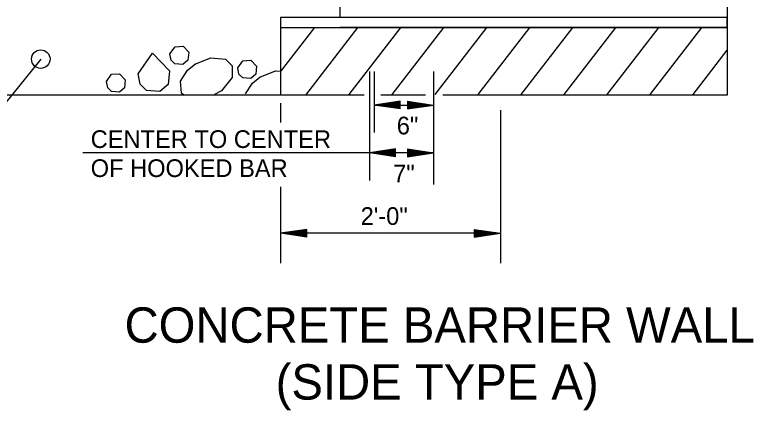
# Model space of a CAD drawing. Extents: x 714919 to 718439, y 1619644 to 1621844.
# Drawn here: x 717627.5 to 718060.8, y 1620274.3 to 1620506.3 of the extents above; entities that cross this region are included whole.
import ezdxf

# ---------------------------------------------------------------- set-up
doc = ezdxf.new("R2010")
doc.units = 0
for name, color, linetype in [('R_Annotation', 7, 'Continuous'), ('R_Dimension', 7, 'Continuous'), ('T_Drafting', 7, 'Continuous')]:
    doc.layers.add(name, color=color, linetype=linetype)

msp = doc.modelspace()

# ---------------------------------------------------------------- linework, layer by layer
at = {"layer": 'R_Annotation'}
msp.add_line((717642.78, 1620480.25), (717587.69, 1620412.31), dxfattribs=at)
msp.add_circle((717642.78, 1620480.25), 5.43, dxfattribs=at)
at = {"layer": 'R_Dimension'}
for p, q in [((717835.7, 1620472.99), (717835.7, 1620409.04)), ((717838.43, 1620472.99), (717838.43, 1620437.15)), ((717873.25, 1620472.99), (717873.25, 1620434.82)), ((717853.72, 1620455.64), (717838.43, 1620453.31)), ((717853.72, 1620455.3), (717840.93, 1620453.31)), ((717853.72, 1620454.86), (717843.61, 1620453.31)), ((717853.72, 1620451.06), (717853.72, 1620455.64)), ((717857.95, 1620455.64), (717873.25, 1620453.31)), ((717857.95, 1620455.64), (717857.95, 1620451.06)), ((717857.95, 1620455.64), (717873.25, 1620453.31)), ((717857.95, 1620455.64), (717857.95, 1620451.06)), ((717857.95, 1620455.3), (717870.74, 1620453.31)), ((717857.95, 1620455.3), (717870.74, 1620453.31)), ((717857.95, 1620454.86), (717868.06, 1620453.31)), ((717857.95, 1620454.86), (717868.06, 1620453.31)), ((717783.48, 1620454.51), (717783.48, 1620443.02)), ((717853.72, 1620451.06), (717838.43, 1620453.31)), ((717838.43, 1620453.31), (717869.36, 1620453.31)), ((717853.72, 1620451.41), (717840.93, 1620453.31)), ((717853.72, 1620451.84), (717843.61, 1620453.31)), ((717853.72, 1620454.52), (717846.12, 1620453.31)), ((717853.72, 1620452.19), (717846.12, 1620453.31)), ((717853.72, 1620454.09), (717848.71, 1620453.31)), ((717853.72, 1620452.62), (717848.71, 1620453.31)), ((717853.72, 1620453.74), (717851.3, 1620453.31)), ((717853.72, 1620452.96), (717851.3, 1620453.31)), ((717857.95, 1620454.52), (717865.56, 1620453.31)), ((717857.95, 1620454.52), (717865.56, 1620453.31)), ((717857.95, 1620454.09), (717862.96, 1620453.31)), ((717857.95, 1620454.09), (717862.96, 1620453.31)), ((717857.95, 1620453.74), (717860.37, 1620453.31)), ((717857.95, 1620453.74), (717860.37, 1620453.31)), ((717857.95, 1620451.06), (717873.25, 1620453.31)), ((717857.95, 1620452.62), (717862.96, 1620453.31)), ((717857.95, 1620451.84), (717868.06, 1620453.31)), ((717857.95, 1620451.41), (717870.74, 1620453.31)), ((717857.95, 1620452.19), (717865.56, 1620453.31)), ((717857.95, 1620452.96), (717860.37, 1620453.31)), ((717857.95, 1620451.06), (717873.25, 1620453.31)), ((717857.95, 1620452.62), (717862.96, 1620453.31)), ((717857.95, 1620451.84), (717868.06, 1620453.31)), ((717857.95, 1620451.41), (717870.74, 1620453.31)), ((717857.95, 1620452.19), (717865.56, 1620453.31)), ((717857.95, 1620452.96), (717860.37, 1620453.31)), ((717912.47, 1620450.4), (717912.47, 1620360.51)), ((717873.25, 1620434.82), (717873.25, 1620406.71)), ((717873.25, 1620425.2), (717667.38, 1620425.2)), ((717850.99, 1620427.53), (717835.7, 1620425.2)), ((717850.99, 1620422.95), (717835.7, 1620425.2)), ((717850.99, 1620427.19), (717838.2, 1620425.2)), ((717850.99, 1620423.3), (717838.2, 1620425.2)), ((717850.99, 1620426.75), (717840.88, 1620425.2)), ((717850.99, 1620423.73), (717840.88, 1620425.2)), ((717850.99, 1620426.41), (717843.39, 1620425.2)), ((717850.99, 1620424.08), (717843.39, 1620425.2)), ((717850.99, 1620425.98), (717845.98, 1620425.2)), ((717850.99, 1620424.51), (717845.98, 1620425.2)), ((717850.99, 1620425.63), (717848.57, 1620425.2)), ((717850.99, 1620424.85), (717848.57, 1620425.2)), ((717850.99, 1620422.95), (717850.99, 1620427.53)), ((717857.95, 1620427.53), (717873.25, 1620425.2)), ((717857.95, 1620427.53), (717857.95, 1620422.95)), ((717857.95, 1620427.53), (717873.25, 1620425.2)), ((717857.95, 1620427.53), (717857.95, 1620422.95)), ((717857.95, 1620427.19), (717870.74, 1620425.2)), ((717857.95, 1620427.19), (717870.74, 1620425.2)), ((717857.95, 1620426.75), (717868.06, 1620425.2)), ((717857.95, 1620426.75), (717868.06, 1620425.2)), ((717857.95, 1620426.41), (717865.56, 1620425.2)), ((717857.95, 1620426.41), (717865.56, 1620425.2)), ((717857.95, 1620425.98), (717862.96, 1620425.2)), ((717857.95, 1620425.98), (717862.96, 1620425.2)), ((717857.95, 1620425.63), (717860.37, 1620425.2)), ((717857.95, 1620425.63), (717860.37, 1620425.2)), ((717857.95, 1620422.95), (717873.25, 1620425.2)), ((717857.95, 1620424.51), (717862.96, 1620425.2)), ((717857.95, 1620423.73), (717868.06, 1620425.2)), ((717857.95, 1620423.3), (717870.74, 1620425.2)), ((717857.95, 1620424.08), (717865.56, 1620425.2)), ((717857.95, 1620424.85), (717860.37, 1620425.2)), ((717857.95, 1620422.95), (717873.25, 1620425.2)), ((717857.95, 1620424.51), (717862.96, 1620425.2)), ((717857.95, 1620423.73), (717868.06, 1620425.2)), ((717857.95, 1620423.3), (717870.74, 1620425.2)), ((717857.95, 1620424.08), (717865.56, 1620425.2)), ((717857.95, 1620424.85), (717860.37, 1620425.2)), ((717783.48, 1620405.26), (717783.48, 1620360.51)), ((717798.86, 1620380.38), (717783.48, 1620378.05)), ((717798.86, 1620380.38), (717783.48, 1620378.05)), ((717898.99, 1620378.05), (717783.48, 1620378.05)), ((717798.86, 1620375.8), (717783.48, 1620378.05)), ((717798.86, 1620375.8), (717783.48, 1620378.05)), ((717798.86, 1620379.95), (717786.07, 1620378.05)), ((717798.86, 1620379.95), (717786.07, 1620378.05)), ((717798.86, 1620376.15), (717786.07, 1620378.05)), ((717798.86, 1620376.15), (717786.07, 1620378.05)), ((717798.86, 1620379.6), (717788.75, 1620378.05)), ((717798.86, 1620379.6), (717788.75, 1620378.05)), ((717798.86, 1620376.58), (717788.75, 1620378.05)), ((717798.86, 1620376.58), (717788.75, 1620378.05)), ((717798.86, 1620379.26), (717791.25, 1620378.05)), ((717798.86, 1620379.26), (717791.25, 1620378.05)), ((717798.86, 1620376.92), (717791.25, 1620378.05)), ((717798.86, 1620376.92), (717791.25, 1620378.05)), ((717798.86, 1620378.82), (717793.84, 1620378.05)), ((717798.86, 1620378.82), (717793.84, 1620378.05)), ((717798.86, 1620377.27), (717793.84, 1620378.05)), ((717798.86, 1620377.27), (717793.84, 1620378.05)), ((717798.86, 1620378.48), (717796.35, 1620378.05)), ((717798.86, 1620378.48), (717796.35, 1620378.05)), ((717798.86, 1620377.7), (717796.35, 1620378.05)), ((717798.86, 1620377.7), (717796.35, 1620378.05)), ((717798.86, 1620375.8), (717798.86, 1620380.38)), ((717798.86, 1620375.8), (717798.86, 1620380.38)), ((717897.09, 1620380.38), (717912.47, 1620378.05)), ((717897.09, 1620380.38), (717897.09, 1620375.8)), ((717897.09, 1620379.95), (717909.97, 1620378.05)), ((717897.09, 1620379.6), (717907.2, 1620378.05)), ((717897.09, 1620379.26), (717904.7, 1620378.05)), ((717897.09, 1620378.82), (717902.1, 1620378.05)), ((717897.09, 1620378.48), (717899.6, 1620378.05)), ((717897.09, 1620375.8), (717912.47, 1620378.05)), ((717897.09, 1620377.27), (717902.1, 1620378.05)), ((717897.09, 1620376.58), (717907.2, 1620378.05)), ((717897.09, 1620376.15), (717909.97, 1620378.05)), ((717897.09, 1620376.92), (717904.7, 1620378.05)), ((717897.09, 1620377.7), (717899.6, 1620378.05))]:
    msp.add_line(p, q, dxfattribs=at)
at = {"layer": 'T_Drafting'}
for p, q in [((717818.3, 1620579.17), (717818.3, 1620504.64)), ((718045.57, 1620579.17), (718045.57, 1620459.19)), ((718045.57, 1620504.64), (717783.48, 1620504.64)), ((717783.48, 1620504.64), (717783.48, 1620498.77)), ((717783.48, 1620504.64), (717783.48, 1620459.19)), ((718045.57, 1620504.64), (717818.3, 1620504.64)), ((718045.57, 1620498.77), (718045.57, 1620504.64)), ((717783.48, 1620498.77), (718045.57, 1620498.77)), ((717783.48, 1620472.74), (717803.49, 1620498.77)), ((717798.29, 1620459.19), (717828.94, 1620499.07)), ((718045.57, 1620498.77), (717818.3, 1620498.77)), ((717823.74, 1620459.49), (717854.17, 1620499.07)), ((717848.97, 1620459.49), (717879.39, 1620499.07)), ((717874.19, 1620459.49), (717904.62, 1620499.07)), ((717899.42, 1620459.49), (717929.84, 1620499.07)), ((717924.64, 1620459.49), (717955.07, 1620499.07)), ((717949.87, 1620459.49), (717980.3, 1620499.07)), ((717975.09, 1620459.49), (718005.52, 1620499.07)), ((718000.32, 1620459.49), (718030.75, 1620499.07)), ((718025.55, 1620459.49), (718045.57, 1620485.54)), ((717832.44, 1620459.19), (717459.87, 1620459.19)), ((717868.56, 1620459.19), (717842.27, 1620459.19)), ((718045.57, 1620459.19), (717878.6, 1620459.19))]:
    msp.add_line(p, q, dxfattribs=at)
for points in [[(717718.58, 1620483.29), (717721.56, 1620487.53), (717726.32, 1620487.81), (717729.62, 1620484.37), (717729.15, 1620479.57), (717726.21, 1620477.12), (717721.51, 1620477.46), (717719.3, 1620479.61), (717718.58, 1620483.29)], [(717699.9, 1620471.62), (717708.39, 1620483.71)], [(717708.39, 1620483.71), (717718.31, 1620473.42), (717717.51, 1620465.41), (717712.61, 1620461.34), (717704.78, 1620461.9), (717701.09, 1620465.48), (717699.9, 1620471.62)], [(717733.24, 1620477.27), (717742.53, 1620480.96), (717751.07, 1620480.22), (717755.13, 1620476.36), (717755, 1620469.43), (717748.84, 1620461.56), (717744.75, 1620459.51)], [(717726.81, 1620459.16), (717725.3, 1620460.23), (717724.82, 1620467.38), (717728.92, 1620473.77), (717733.61, 1620477.51)], [(717758.35, 1620475.09), (717761.33, 1620479.33), (717766.09, 1620479.6), (717769.4, 1620476.17), (717768.92, 1620471.36), (717765.98, 1620468.92), (717761.28, 1620469.25), (717759.07, 1620471.4), (717758.35, 1620475.08)], [(717771.23, 1620469.64), (717780.52, 1620473.33), (717782.85, 1620473.13)], [(717681.32, 1620467.12), (717684.3, 1620471.36), (717689.06, 1620471.63), (717692.37, 1620468.2), (717691.89, 1620463.4), (717688.95, 1620460.95), (717684.25, 1620461.29), (717682.04, 1620463.44), (717681.32, 1620467.12)], [(717762.9, 1620459.88), (717766.91, 1620466.14), (717771.6, 1620469.88)]]:
    msp.add_lwpolyline(points, dxfattribs=at)

# ---------------------------------------------------------------- texts
at = {"layer": 'R_Annotation'}
for s, p in [('CONCRETE BARRIER WALL ', (717691.93, 1620313.88)), ('(SIDE TYPE A) ', (717780.59, 1620280.5))]:
    msp.add_text(s, height=20.736, dxfattribs=at).set_placement(p)
at = {"layer": 'R_Dimension'}
for s, height, p in [('6"', 10.369, (717851.65, 1620436.11)), ('CENTER TO CENTER', 10.3685, (717672.08, 1620428.13)), ('OF HOOKED BAR', 10.3685, (717672.08, 1620411.1)), ('7"', 10.369, (717849.53, 1620407.9)), ('2\'-0"', 10.369, (717830.47, 1620382.99))]:
    msp.add_text(s, height=height, dxfattribs=at).set_placement(p)

doc.saveas('drawing.dxf')
